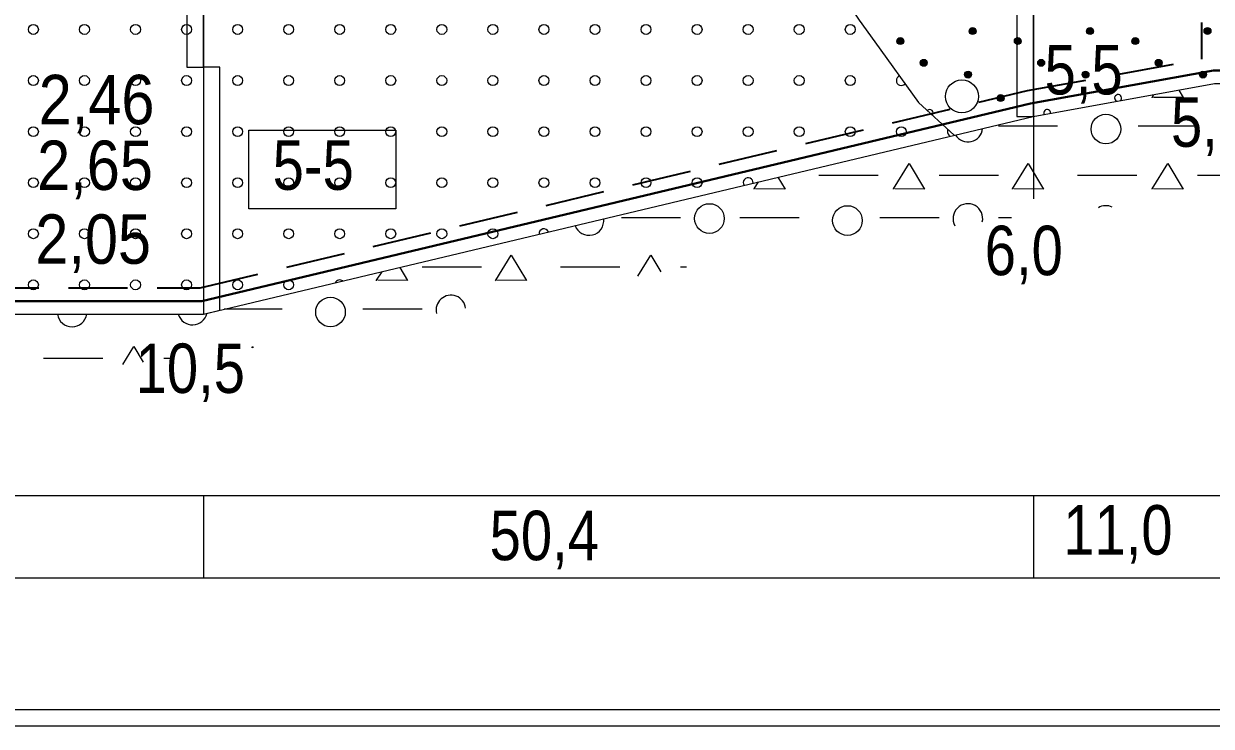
# Model space of a CAD drawing. Extents: x 640121 to 640955, y 6441885 to 6442246.
# Drawn here: x 640200.9 to 640273, y 6441889.4 to 6441932 of the extents above; entities that cross this region are included whole.
import ezdxf
from ezdxf.enums import TextEntityAlignment as Align

# ---------------------------------------------------------------- set-up
doc = ezdxf.new("R2010")
doc.units = 0
doc.header["$LTSCALE"] = 1.2
doc.linetypes.add('MEDIUM_DASHED', pattern=[4.5, 3, -1.5])
for name, color, linetype, lineweight in [('30', 7, 'Continuous', 13), ('31', 7, 'Continuous', 13), ('32', 7, 'Continuous', 13), ('33', 7, 'Continuous', 13), ('35', 7, 'Continuous', 35), ('43', 7, 'Continuous', 13), ('44', 7, 'Continuous', 13), ('46', 7, 'Continuous', 13), ('47', 7, 'Continuous', 13), ('50', 7, 'Continuous', 13)]:
    doc.layers.add(name, color=color, linetype=linetype, lineweight=lineweight)

msp = doc.modelspace()

# ---------------------------------------------------------------- hatches: boundary and pattern name
at = {"layer": '44'}
for points in [[(640258.725, 6441931.596, 1), (640258.305, 6441931.596, 1)], [(640265.858, 6441931.596, 1), (640265.438, 6441931.596, 1)], [(640272.991, 6441931.596, 1), (640272.571, 6441931.596, 1)], [(640254.339, 6441930.99, 1), (640253.919, 6441930.99, 1)], [(640261.472, 6441930.99, 1), (640261.052, 6441930.99, 1)], [(640268.605, 6441930.99, 1), (640268.185, 6441930.99, 1)], [(640255.758, 6441929.668, 1), (640255.338, 6441929.668, 1)], [(640262.891, 6441929.668, 1), (640262.471, 6441929.668, 1)], [(640270.024, 6441929.668, 1), (640269.604, 6441929.668, 1)], [(640258.451, 6441928.952, 1), (640258.031, 6441928.952, 1)], [(640265.584, 6441928.952, 1), (640265.164, 6441928.952, 1)], [(640272.717, 6441928.952, 1), (640272.297, 6441928.952, 1)], [(640260.428, 6441927.533, 1), (640260.008, 6441927.533, 1)]]:
    msp.add_hatch(color=256, dxfattribs=at).paths.add_polyline_path(points)

# ---------------------------------------------------------------- linework, layer by layer
at = {"layer": '30'}
for p, q in [((640211.81, 6441903.41), (640211.81, 6441898.41)), ((640262.21, 6441903.41), (640262.21, 6441898.41))]:
    msp.add_line(p, q, dxfattribs=at)
for points in [[(640132.29, 6441898.41), (640465.01, 6441898.41), (640465.01, 6442028.41)], [(640132.29, 6441898.41), (640132.29, 6441903.41), (640465.01, 6441903.41)]]:
    msp.add_lwpolyline(points, dxfattribs=at)
at = {"layer": '31'}
for points in [[(640219.5, 6441962.07), (640223.33, 6441960.67), (640227.82, 6441958.13), (640230.7, 6441955.94), (640234.62, 6441952.84), (640238.88, 6441948.92), (640244.06, 6441942.93), (640248.32, 6441937.29), (640250.05, 6441934.64), (640251.62, 6441932.26), (640252.58, 6441930.95), (640255.23, 6441927.27), (640257.4, 6441925.27)], [(640160.01, 6441914.1), (640175.01, 6441914.41), (640211.81, 6441914.41), (640262.19, 6441926.41), (640273.21, 6441928.41), (640281.2, 6441928.41), (640286.29, 6441927.68), (640289.79, 6441927.25), (640293.57, 6441926.53), (640298.03, 6441925.47), (640301.11, 6441924.59), (640304.79, 6441923.7)]]:
    msp.add_lwpolyline(points, dxfattribs=at)
at = {"layer": '32', "lineweight": 25}
for p, q in [((640211.81, 6442019.41), (640211.81, 6441914.41)), ((640262.21, 6441981.41), (640262.21, 6441921.41))]:
    msp.add_line(p, q, dxfattribs=at)
at = {"layer": '33'}
for points in [[(640261.21, 6441967.4), (640261.21, 6441926.41), (640262.19, 6441926.41), (640262.19, 6441926.41), (640262.21, 6441926.41), (640262.21, 6441967.41), (640261.72, 6441967.41)], [(640210.81, 6441951.41), (640210.81, 6441929.41), (640211.81, 6441929.41), (640211.81, 6441951.41)], [(640212.81, 6441914.65), (640212.81, 6441929.41), (640211.81, 6441929.41), (640211.81, 6441914.41)]]:
    msp.add_lwpolyline(points, close=True, dxfattribs=at)
at = {"layer": '33', "lineweight": 25}
msp.add_lwpolyline([(640214.56, 6441925.58), (640223.49, 6441925.58), (640223.49, 6441920.8), (640214.56, 6441920.8)], close=True, dxfattribs=at)
at = {"layer": '35', "linetype": 'MEDIUM_DASHED'}
msp.add_line((640272.41, 6441953.71), (640272.41, 6441929.89), dxfattribs=at)
msp.add_lwpolyline([(640176.61, 6441916.01), (640211.62, 6441916.01), (640261.86, 6441927.98), (640272.41, 6441929.89)], dxfattribs=at)
at = {"layer": '35', "lineweight": 40}
msp.add_lwpolyline([(640175.81, 6441915.21), (640211.72, 6441915.21), (640262.03, 6441927.19), (640273.14, 6441929.21), (640281.19, 6441929.21)], dxfattribs=at)
at = {"layer": '43'}
for centre in [(640201.488, 6441931.693), (640204.588, 6441931.693), (640207.688, 6441931.693), (640210.788, 6441931.693), (640213.888, 6441931.693), (640216.988, 6441931.693), (640220.088, 6441931.693), (640223.188, 6441931.693), (640226.288, 6441931.693), (640229.388, 6441931.693), (640232.488, 6441931.693), (640235.588, 6441931.693), (640238.688, 6441931.693), (640241.788, 6441931.693), (640244.888, 6441931.693), (640247.988, 6441931.693), (640251.088, 6441931.693), (640201.488, 6441928.593), (640204.588, 6441928.593), (640207.688, 6441928.593), (640210.788, 6441928.593), (640213.888, 6441928.593), (640216.988, 6441928.593), (640220.088, 6441928.593), (640223.188, 6441928.593), (640226.288, 6441928.593), (640229.388, 6441928.593), (640232.488, 6441928.593), (640235.588, 6441928.593), (640238.688, 6441928.593), (640241.788, 6441928.593), (640244.888, 6441928.593), (640247.988, 6441928.593), (640251.088, 6441928.593), (640201.488, 6441925.493), (640204.588, 6441925.493), (640207.688, 6441925.493), (640210.788, 6441925.493), (640213.888, 6441925.493), (640216.988, 6441925.493), (640220.088, 6441925.493), (640223.188, 6441925.493), (640226.288, 6441925.493), (640229.388, 6441925.493), (640232.488, 6441925.493), (640235.588, 6441925.493), (640238.688, 6441925.493), (640241.788, 6441925.493), (640244.888, 6441925.493), (640247.988, 6441925.493), (640251.088, 6441925.493), (640254.188, 6441925.493), (640201.488, 6441922.393), (640204.588, 6441922.393), (640207.688, 6441922.393), (640210.788, 6441922.393), (640213.888, 6441922.393), (640216.988, 6441922.393), (640220.088, 6441922.393), (640223.188, 6441922.393), (640226.288, 6441922.393), (640229.388, 6441922.393), (640232.488, 6441922.393), (640235.588, 6441922.393), (640238.688, 6441922.393), (640241.788, 6441922.393), (640201.488, 6441919.293), (640204.588, 6441919.293), (640207.688, 6441919.293), (640210.788, 6441919.293), (640213.888, 6441919.293), (640216.988, 6441919.293), (640220.088, 6441919.293), (640223.188, 6441919.293), (640226.288, 6441919.293), (640229.388, 6441919.293), (640201.488, 6441916.193), (640204.588, 6441916.193), (640207.688, 6441916.193), (640210.788, 6441916.193), (640213.888, 6441916.193), (640216.988, 6441916.193)]:
    msp.add_circle(centre, 0.3, dxfattribs=at)
for centre, start, end in [((640254.188, 6441928.593), 111.50728, 319.90611), ((640257.288, 6441925.493), 154.48816, 247.93529), ((640244.888, 6441922.393), 353.55227, 213.24258), ((640232.488, 6441919.293), 21.1873, 185.60755), ((640220.088, 6441916.193), 51.02745, 155.7674)]:
    msp.add_arc(centre, 0.3, start, end, dxfattribs=at)
at = {"layer": '44'}
for centre in [(640258.515, 6441931.596), (640265.648, 6441931.596), (640272.781, 6441931.596), (640254.129, 6441930.99), (640261.262, 6441930.99), (640268.395, 6441930.99), (640255.548, 6441929.668), (640262.681, 6441929.668), (640269.814, 6441929.668), (640258.241, 6441928.952), (640265.374, 6441928.952), (640272.507, 6441928.952), (640260.218, 6441927.533)]:
    msp.add_circle(centre, 0.21, dxfattribs=at)
for centre, start, end in [((640267.351, 6441927.533), 308.77866, 251.79617), ((640255.912, 6441926.625), 320.33879, 134.36781), ((640263.045, 6441926.625), 353.75876, 206.81607)]:
    msp.add_arc(centre, 0.21, start, end, dxfattribs=at)
at = {"layer": '46'}
for p, q in [((640263.68, 6441925.82), (640260.08, 6441925.82)), ((640272.18, 6441925.82), (640268.58, 6441925.82)), ((640252.79, 6441922.83), (640249.19, 6441922.83)), ((640260.08, 6441922.82), (640256.48, 6441922.82)), ((640268.48, 6441922.83), (640264.88, 6441922.83)), ((640275.78, 6441922.82), (640272.18, 6441922.82)), ((640240.79, 6441920.27), (640237.19, 6441920.27)), ((640247.99, 6441920.26), (640244.39, 6441920.26)), ((640256.48, 6441920.27), (640252.88, 6441920.27)), ((640260.88, 6441920.26), (640260.08, 6441920.26)), ((640228.69, 6441917.27), (640225.09, 6441917.27)), ((640237.09, 6441917.27), (640233.49, 6441917.27)), ((640241.15, 6441917.27), (640240.79, 6441917.27)), ((640216.6, 6441914.71), (640213.07, 6441914.71)), ((640225.09, 6441914.72), (640221.49, 6441914.72)), ((640205.7, 6441911.72), (640202.1, 6441911.72)), ((640209.86, 6441911.72), (640209.4, 6441911.72))]:
    msp.add_line(p, q, dxfattribs=at)
for points in [[(640269.42, 6441927.55), (640269.42, 6441927.57), (640269.52, 6441927.74)], [(640271.03, 6441928.01), (640271.3, 6441927.56), (640269.5, 6441927.57)], [(640253.72, 6441922), (640253.72, 6441922.02), (640254.67, 6441923.55), (640255.6, 6441922.01), (640253.8, 6441922.02)], [(640260.94, 6441922), (640260.95, 6441922.02), (640261.89, 6441923.55), (640262.82, 6441922.01), (640261.02, 6441922.02)], [(640269.42, 6441922), (640269.42, 6441922.02), (640270.37, 6441923.55), (640271.3, 6441922.01), (640269.5, 6441922.02)], [(640246.7, 6441922.72), (640247.13, 6441922.01), (640245.33, 6441922.02)], [(640245.25, 6441922), (640245.25, 6441922.02), (640245.51, 6441922.44)], [(640229.55, 6441916.44), (640229.56, 6441916.47), (640230.5, 6441918), (640231.43, 6441916.46), (640229.63, 6441916.47)], [(640238.19, 6441916.72), (640238.98, 6441918), (640239.59, 6441916.98)], [(640222.33, 6441916.44), (640222.33, 6441916.47), (640222.66, 6441916.99)], [(640223.73, 6441917.25), (640224.21, 6441916.46), (640222.41, 6441916.47)], [(640206.91, 6441911.35), (640207.59, 6441912.44), (640208.15, 6441911.5)], [(640214.76, 6441912.37), (640214.81, 6441912.44), (640214.84, 6441912.38)]]:
    msp.add_lwpolyline(points, dxfattribs=at)
for centre in [(640266.613, 6441925.651), (640242.536, 6441920.219), (640250.918, 6441920.097), (640219.528, 6441914.542)]:
    msp.add_circle(centre, 0.9, dxfattribs=at)
for centre, start, end in [((640258.231, 6441925.773), 212.78046, 354.01439), ((640258.231, 6441920.219), 346.72032, 209.53989), ((640266.613, 6441920.097), 65.16067, 120.76121), ((640235.223, 6441920.097), 200.27149, 6.52336), ((640226.841, 6441914.664), 7.19171, 193.86386), ((640203.833, 6441914.542), 188.48564, 351.51436), ((640211.146, 6441914.664), 196.45695, 346.85783)]:
    msp.add_arc(centre, 0.9, start, end, dxfattribs=at)
at = {"layer": '47'}
msp.add_circle((640257.87, 6441927.632), 1, dxfattribs=at)
at = {"layer": '50', "lineweight": 25}
msp.add_lwpolyline([(640121.33, 6442246.16), (640955.23, 6442246.16), (640955.23, 6441889.4), (640121.33, 6441889.4)], close=True, dxfattribs=at)
at = {"layer": '50'}
msp.add_lwpolyline([(640122.33, 6442245.16), (640954.23, 6442245.16), (640954.23, 6441890.4), (640122.33, 6441890.4)], close=True, dxfattribs=at)

# ---------------------------------------------------------------- texts
at = {"layer": '30', "width": 0.85}
for s, p in [('50,4', (640232.51, 6441899.48)), ('11,0', (640267.34, 6441899.82))]:
    msp.add_text(s, height=3, dxfattribs=at).set_placement(p, align=Align.CENTER)
at = {"layer": '32'}
for s, width, p in [('5,5', 0.85, (640265.26, 6441927.75)), ('2,46', 0.9, (640205.325, 6441925.94)), ('5,0', 0.85, (640272.935, 6441924.57)), ('2,65', 0.9, (640205.23, 6441921.95)), ('2,05', 0.9, (640205.115, 6441917.47)), ('6,0', 0.85, (640261.625, 6441916.78)), ('10,5', 0.85, (640211.015, 6441909.63))]:
    msp.add_text(s, height=3, dxfattribs=dict(at, width=width)).set_placement(p, align=Align.CENTER)
at = {"layer": '33', "width": 0.85}
msp.add_text('5-5', height=3, dxfattribs=at).set_placement((640218.48, 6441921.96), align=Align.CENTER)

doc.saveas('drawing.dxf')
